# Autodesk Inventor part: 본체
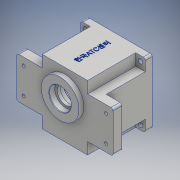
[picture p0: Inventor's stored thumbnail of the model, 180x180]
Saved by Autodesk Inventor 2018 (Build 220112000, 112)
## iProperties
Created: 2020-07
Part Number: 본체
Material: 알루미늄 6061
Document SubType Name: Modeling
Designer: Admin
Density: 2.7 g/cm^3
Appearance: 알루미늄 - 평지
Mass: 876.392 g
Surface Area: 792.122 cm^2
Volume: 324.59 cm^3
Author: Admin
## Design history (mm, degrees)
sketch "스케치1"
  geometry: L1 (47, -47)-(-47, -47); L2 (-47, -47)-(-47, 47); L3 (-47, 47)-(47, 47); L4 (47, 47)-(47, -47); L5 (47, -47)-(-47, 47); L6 (-47, -47)-(47, 47); L7 (70, -30)-(-70, -30); L8 (-70, -30)-(-70, 30); L9 (-70, 30)-(70, 30); L10 (70, 30)-(70, -30); L11 (70, -30)-(-70, 30); L12 (-70, -30)-(70, 30); 1 further point
  constraints: 24 end point, 4 midpoint, 4 parallel, 2 horizontal, 2 perpendicular
  dimensions: "d0" = 94 distance of L2.end L3.end; "d1" = 94 distance of L1.end L2.end; "d2" = 140 distance of L8.end L9.end; "d3" = 60 distance of L7.end L8.end
extrude "돌출1" new body sketch "스케치1" stored distance "d4" = 80; taper "d5" = 0 deg
sketch "스케치2"
  geometry: L1 (94, 0)-(94, -80) reference; L2 (0, 0)-(94, 0) reference; L3 (0, 0)-(0, -80) reference; L4 (94, -80)-(0, -80) reference; L5 (0, -80)-(0, 0) reference; L6 (-23, 0)-(0, 0) reference; L7 (-23, 0)-(-23, -80) reference; L8 (0, -80)-(-23, -80) reference; L9 (94, 0)-(94, -80) reference; L10 (117, -80)-(94, -80) reference; L11 (117, 0)-(117, -80) reference; L12 (94, 0)-(117, 0) reference; L13 (94, 0)-(117, 0); L14 (117, 0)-(117, -67); L15 (117, -67)-(94, -67); L16 (94, -67)-(94, 0); L17 (0, 0)-(-23, 0) reference; L18 (0, -80)-(0, 0) reference; L19 (-23, 0)-(0, 0); L20 (0, 0)-(0, -67); L21 (0, -67)-(-23, -67); L22 (-23, -67)-(-23, 0); 1 further point
  constraints: 16 end point, 4 parallel, 3 point on line, 2 horizontal, 2 perpendicular
  dimensions: "d6" = 13 distance between parallel lines of L10 L15
extrude "돌출2" cut sketch "스케치2" extent not by distance; stored distance "d7" = 80; taper "d8" = 0 deg
sketch "스케치3"
  geometry: L1 (47, 30)-(47, 47) reference; L2 (47, 47)-(-47, 47) reference; L3 (-47, 47)-(-47, 30) reference; L4 (-47, 30)-(-70, 30) reference; L5 (-70, 30)-(-70, -30) reference; L6 (-70, -30)-(-47, -30) reference; L7 (-47, -30)-(-47, -47) reference; L8 (-47, -47)-(47, -47) reference; L9 (47, -47)-(47, -30) reference; L10 (47, -30)-(70, -30) reference; L11 (70, -30)-(70, 30) reference; L12 (70, 30)-(47, 30) reference; L13 (47, 47)-(-47, 47) reference; L14 (-47, 47)-(-33, 47); L15 (-33, 47)-(-33, 30); L16 (-33, 30)-(-47, 30); L17 (-47, 30)-(-47, 47); L18 (47, 47)-(33, 47); L19 (33, 47)-(33, 30); L20 (33, 30)-(47, 30); L21 (47, 30)-(47, 47); L22 (0, -65.8)-(0, 65.8) reference; L23 (-98, 0)-(98, 0) reference; L24 (-47, -47)-(47, -47) reference; L25 (-47, -30)-(-33, -30); L26 (-33, -30)-(-33, -47); L27 (-33, -47)-(-47, -47); L28 (-47, -47)-(-47, -30); L29 (47, -30)-(33, -30); L30 (33, -30)-(33, -47); L31 (33, -47)-(47, -47); L32 (47, -47)-(47, -30); 1 further point
  constraints: 32 end point, 8 parallel, 4 horizontal, 4 perpendicular, 3 symmetric about line, 2 point on line
  dimensions: "d9" = 66 distance between parallel lines of L19 L15
extrude "돌출3" cut sketch "스케치3" distance "d10" = 70; taper "d11" = 0 deg
sketch "스케치4"
  geometry: L1 (-98, 0)-(98, 0) reference; L2 (0, -65.8)-(0, 65.8) reference; 5 further points
  constraints: 4 symmetric about line
  dimensions: "d12" = 80 distance of point (-40, 40) point (40, 40); "d13" = 80 distance of point (40, -40) point (40, 40)
hole "구멍1" sketch "스케치4" at (-40, 40), (40, 40), (-40, -40), (40, -40) diameter "d14" = 7; stored, may be unused: countersink angle "d18" = 90 deg, drill point angle "d20" = 118 deg; dims "d15" = 6, "d16" = 4, "d17" = 2, "d19" = 8
sketch "스케치5"
  geometry: L1 (-33, -30)-(-33, -47) reference; L2 (-33, -47)-(33, -47) reference; L3 (33, -47)-(33, -30) reference; L4 (33, -30)-(70, -30) reference; L5 (70, -30)-(70, 30) reference; L6 (70, 30)-(33, 30) reference; L7 (33, 30)-(33, 47) reference; L8 (33, 47)-(-33, 47) reference; L9 (-33, 47)-(-33, 30) reference; L10 (-33, 30)-(-70, 30) reference; L11 (-70, 30)-(-70, -30) reference; L12 (-70, -30)-(-33, -30) reference; C1 r 27.5 at (0, 11); 1 further point
  constraints: 1 centre point, 1 vertical alignment
  dimensions: "d21" = 55 diameter of C1; "d22" = 11 distance of point (0, 0) C1.centre
extrude "돌출4" join sketch "스케치5" distance "d23" = 7; taper "d24" = 0 deg
sketch "스케치6"
  geometry: L1 (-80, 60)-(-80, 77) reference; L2 (-80, 77)-(-14, 77) reference; L3 (-14, 77)-(-14, 60) reference; L4 (-14, 60)-(23, 60) reference; L5 (23, 60)-(23, 0) reference; L6 (23, 0)-(-14, 0) reference; L7 (-14, 0)-(-14, -17) reference; L8 (-14, -17)-(-80, -17) reference; L9 (-80, -17)-(-80, 0) reference; L10 (-80, 0)-(-117, 0) reference; L11 (-117, 0)-(-117, 60) reference; L12 (-117, 60)-(-80, 60) reference; L13 (-145, 30)-(51, 30) reference; L14 (-47, 95.8)-(-47, -35.8) reference; C1 r 27.5 at (-47, 19) reference; 5 further points
  constraints: 3 symmetric about line
  dimensions: "d25" = 120 distance of point (-107, 11) point (13, 11); "d26" = 38 distance of point (-107, 49) point (-107, 11)
hole "구멍2" sketch "스케치6" at (13, 11), (13, 49), (-107, 11), (-107, 49) diameter "d27" = 4.5; stored, may be unused: countersink angle "d31" = 90 deg, drill point angle "d33" = 118 deg; dims "d28" = 6, "d29" = 10, "d30" = 5, "d32" = 8
sketch "스케치7"
  geometry: L1 (-47, 38.5)-(-47, -16.5) reference; L2 (-40, -16.5)-(-40, 38.5) reference; L3 (-40, 47)-(-40, 30) reference; L4 (30, 47)-(-40, 47) reference; L5 (30, 47)-(30, 30) reference; L6 (-40, 30)-(30, 30) reference; L7 (-64.4, 0)-(57.4, 0) reference; L8 (-47, 38.5)-(-47, -16.5) reference; L9 (-47, 27)-(-38.7, 27); L10 (-38.7, 27)-(-38.7, 11); L11 (-38.7, 11)-(-47, 11); L12 (-47, 11)-(-47, 27); L13 (-38.7, 11)-(-34, 11); L14 (-34, 11)-(-34, 23.5); L15 (-34, 23.5)-(-38.7, 23.5); L16 (-38.7, 23.5)-(-38.7, 11); L17 (-34, 11)-(-24, 11); L18 (-24, 11)-(-24, 28.5); L19 (-24, 28.5)-(-34, 28.5); L20 (-34, 28.5)-(-34, 11); 1 further point
  constraints: 24 end point, 6 parallel, 3 horizontal, 3 perpendicular, 1 point on line
  dimensions: "d34" = 16 distance of L9.end L10.end; "d35" = 12.5 distance between parallel lines of L13 L15; "d36" = 17.5 distance of L17.end L18.end; "d37" = 11 distance between parallel lines of L7 L17; "d38" = 8.3 distance of L9.start L9.end; "d40" = 10 distance of L18.end L19.end; "d73" = 23 distance between parallel lines of L18 L1
revolve "회전1" sketch "스케치7" stored, may be unused: angle "d41" = 90 deg
sketch "스케치8"
  geometry: L1 (-24, 28.5)-(-24, -6.5) reference; L2 (-64.4, 0)-(57.4, 0) reference; L3 (-34, -20)-(-31, -20); L4 (-31, -20)-(-31, -29.5); L5 (-31, -29.5)-(-34, -29.5); L6 (-34, -29.5)-(-34, -20); L7 (-31, -20)-(-24, -20); L8 (-24, -20)-(-24, -31); L9 (-24, -31)-(-31, -31); L10 (-31, -31)-(-31, -20); 1 further point
  constraints: 16 end point, 4 parallel, 2 horizontal, 2 perpendicular, 1 point on line
  dimensions: "d42" = 11 distance of L7.end L8.end; "d43" = 9.5 distance of L5.end L3.start; "d44" = 20 distance between parallel lines of L7 L2; "d45" = 3 distance of L4.end L5.end; "d46" = 7 distance of L8.end L9.end
revolve "회전2" sketch "스케치8" stored, may be unused: angle "d47" = 90 deg
sketch "스케치9"
  geometry: C1 r 43 at (0, 0); 1 further point
  constraints: 1 centre point, 1 coincident
  dimensions: "d48" = 86 diameter of C1
extrude "돌출5" cut sketch "스케치9" distance "d49" = 9; taper "d50" = 0 deg
sketch "스케치10"
  geometry: C1 r 40 at (0, 0); 1 further point
  constraints: 1 centre point, 1 coincident
  dimensions: "d51" = 80 diameter of C1
extrude "돌출6" cut sketch "스케치10" distance "d52" = 55; taper "d53" = 0 deg
sketch "스케치11"
  geometry: C1 r 11 at (0, 20) reference; C2 r 17.5 at (0, -11) reference; C3 r 40 at (0, 0) reference; C4 r 40 at (0, 0); A1 r 21 centre (0, -11) between (-8.978, 7.984) and (8.978, 7.984); A2 r 15 centre (0, 20) between (8.978, 7.984) and (-8.978, 7.984); 1 further point
  constraints: 4 point on circle, 3 centre point, 3 coincident
  dimensions: "d54" = 42 diameter of A1; "d55" = 30 diameter of A2; "d56" = 80 diameter of C4
extrude "돌출7" cut sketch "스케치11" distance "d57" = 7; taper "d58" = 0 deg
sketch "스케치12" dims "d60" = 72
  geometry: L1 (-98, 0)-(98, 0) reference; L2 (0, 65.8)-(0, -65.8) reference; L3 (39.799, -4)-(36, -4); L4 (39.799, 4)-(36, 4); L5 (-39.799, -4)-(-36, -4); L6 (-39.799, 4)-(-36, 4); A1 r 21 centre (0, -11) between (-8.978, 7.984) and (8.978, 7.984) reference; A2 r 15 centre (0, 20) between (8.978, 7.984) and (-8.978, 7.984) reference; A3 r 40 centre (0, 0) between (39.799, 4) and (39.799, -4) reference; A4 r 4 centre (36, 0) between (36, 4) and (36, -4); A5 r 40 centre (0, 0) between (39.799, -4) and (39.799, 4); A6 r 4 centre (-36, 0) between (-36, -4) and (-36, 4); A7 r 40 centre (0, 0) between (-39.799, 4) and (-39.799, -4); 2 further points
  constraints: 10 point on circle, 8 end point, 5 symmetric about line, 4 centre point, 2 coincident, 2 horizontal, 2 tangent, 1 horizontal alignment, 1 point on line, 4 other
  dimensions: "d59" = 8 diameter of A4
extrude "돌출8" join sketch "스케치12" stored distance "d61" = 7; taper "d62" = 0 deg
sketch "스케치13"
  geometry: L1 (-39.799, -4)-(-36, -4) reference; L2 (-36, 4)-(-39.799, 4) reference; L3 (36, 4)-(39.799, 4) reference; L4 (39.799, -4)-(36, -4) reference; C1 r 43 at (0, 0) reference; A1 r 40 centre (0, 0) between (-39.799, -4) and (39.799, -4) reference; A2 r 4 centre (-36, 0) between (-36, -4) and (-36, 4) reference; A3 r 40 centre (0, 0) between (39.799, 4) and (-39.799, 4) reference; A4 r 4 centre (36, 0) between (36, 4) and (36, -4) reference; 3 further points
  constraints: 2 coincident
hole "구멍3" sketch "스케치13" at (36, 0), (-36, 0) diameter "d63" = 3.242; stored, may be unused: countersink angle "d67" = 90 deg, drill point angle "d69" = 118 deg; dims "d64" = 7, "d65" = 10, "d66" = 5, "d68" = 9
chamfer "모따기1" distance "d70" = 0.8; stored, may be unused: second distance "d71" = 2, angle "d72" = 30 deg
chamfer "모따기2" distance "d74" = 1; stored, may be unused: second distance "d75" = 2, angle "d76" = 30 deg
fillet "모깎기1" dims "d77" = 3
sketch "스케치14"
  geometry: L1 (77, 80)-(77, 70) reference; L2 (-11, 80)-(77, 80) reference; L3 (-11, 70)-(-11, 80) reference; L4 (-11, 70)-(0, 70) reference; L5 (0, 70)-(0, 0) reference; L6 (66, 0)-(0, 0) reference; L7 (66, 0)-(66, 70) reference; L8 (66, 70)-(77, 70) reference; 2 further points
  constraints: 1 coincident, 1 other
  dimensions: "d78" = 40 distance from line of L2 point (33, 40)
feature "엠보싱1" sketch "스케치14" dims "d79" = 0.5, "d80" = 0
node "솔리드1"
node "투영된 루프1"
node "투영된 루프2"
node "투영된 루프3"
node "투영된 루프4"
node "투영된 루프5"
node "투영된 루프6"
node "투영된 루프7"
node "투영된 루프8"
node "투영된 루프9"
node "투영된 루프10"
node "투영된 루프11"
node "투영된 루프12"
